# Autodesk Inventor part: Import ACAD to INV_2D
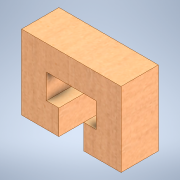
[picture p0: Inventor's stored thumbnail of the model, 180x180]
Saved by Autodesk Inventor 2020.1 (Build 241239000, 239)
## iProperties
Created: 2019-11
Part Number: Import ACAD to INV_2D
Material: Wood (Cherry)
Document SubType Name: Modeling
Designer: Synergysoft Dell02
Density: 0.63 g/cm^3
Appearance: Cherry - Natural Low Gloss
Author: Synergysoft Dell02
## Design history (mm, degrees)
sketch "Sketch1"
  geometry: L1 (0, 0)-(30, 0); L2 (30, 0)-(30, 20); L3 (30, 20)-(20, 20); L4 (20, 20)-(20, 40); L5 (20, 40)-(60, 40); L6 (60, 40)-(60, 20); L7 (60, 20)-(50, 20); L8 (50, 20)-(50, 0); L9 (50, 0)-(80, 0); L10 (80, 0)-(80, 60); L11 (80, 60)-(0, 60); L12 (0, 60)-(0, 0); L13 (133.795, 0)-(163.795, 0); L14 (163.795, 0)-(163.795, 60); L15 (163.795, 60)-(133.795, 60); L16 (133.795, 60)-(133.795, 0); L17 (133.795, 40)-(163.795, 40); L18 (133.795, 20)-(163.795, 20); 1 further point
  constraints: 36 end point, 8 perpendicular, 7 collinear, 7 parallel, 4 point on line, 1 coincident, 1 horizontal
  dimensions: "d15" = 60 distance of L11.end L1.start; "d17" = 40 distance of L4.end L5.end; "d19" = 30 distance of L1.start L1.end; "d21" = 80 distance of L1.start L9.end; "d23" = 20 distance of L1.end L8.end; "d27" = 20 distance of L3.end L4.end; "d29" = 30 distance of L13.start L13.end; "d32" = 20 distance between parallel lines of L1 L3; "d33" = 20 distance between parallel lines of L12 L4; "d34" = 53.79489 distance between parallel lines of L16 L10; "d35" = 60 distance between parallel lines of L13 L15
extrude "Extrusion1" new body sketch "Sketch1" distance "d30" = 30 (= d29); taper "d31" = 0 deg
body "Solid1"
